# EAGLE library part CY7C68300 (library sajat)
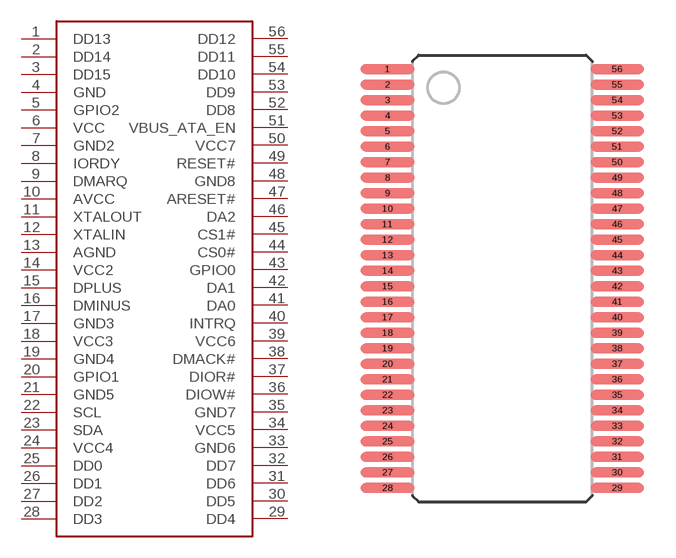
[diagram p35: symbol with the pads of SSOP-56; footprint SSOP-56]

Designator prefix -

## CY7C68300  [SSOP-56]
1  DD13
2  DD14
3  DD15
4  GND
5  GPIO2
6  VCC
7  GND2
8  IORDY
9  DMARQ
10  AVCC
11  XTALOUT
12  XTALIN
13  AGND
14  VCC2
15  DPLUS
16  DMINUS
17  GND3
18  VCC3
19  GND4
20  GPIO1
21  GND5
22  SCL
23  SDA
24  VCC4
25  DD0
26  DD1
27  DD2
28  DD3
29  DD4
30  DD5
31  DD6
32  DD7
33  GND6
34  VCC5
35  GND7
36  DIOW#
37  DIOR#
38  DMACK#
39  VCC6
40  INTRQ
41  DA0
42  DA1
43  GPIO0
44  CS0#
45  CS1#
46  DA2
47  ARESET#
48  GND8
49  RESET#
50  VCC7
51  VBUS_ATA_EN
52  DD8
53  DD9
54  DD10
55  DD11
56  DD12

## Footprint SSOP-56 (pad centres in mm)
56-lead Shrunk Small Outline Package SSOP56
smd 2.2 x 0.4: 1 -4.7,8.572; 2 -4.7,7.938; 3 -4.7,7.303; 4 -4.7,6.668; 5 -4.7,6.032; 6 -4.7,5.397; 7 -4.7,4.763; 8 -4.7,4.128; 9 -4.7,3.493; 10 -4.7,2.857; 11 -4.7,2.223; 12 -4.7,1.587; 13 -4.7,0.953; 14 -4.7,0.318; 15 -4.7,-0.318; 16 -4.7,-0.953; 17 -4.7,-1.587; 18 -4.7,-2.223; 19 -4.7,-2.857; 20 -4.7,-3.493; 21 -4.7,-4.128; 22 -4.7,-4.763; 23 -4.7,-5.397; 24 -4.7,-6.032; 25 -4.7,-6.668; 26 -4.7,-7.303; 27 -4.7,-7.938; 28 -4.7,-8.572; 29 4.7,-8.572; 30 4.7,-7.938; 31 4.7,-7.303; 32 4.7,-6.668; 33 4.7,-6.032; 34 4.7,-5.397; 35 4.7,-4.763; 36 4.7,-4.128; 37 4.7,-3.493; 38 4.7,-2.857; 39 4.7,-2.223; 40 4.7,-1.587; 41 4.7,-0.953; 42 4.7,-0.318; 43 4.7,0.318; 44 4.7,0.953; 45 4.7,1.587; 46 4.7,2.223; 47 4.7,2.857; 48 4.7,3.493; 49 4.7,4.128; 50 4.7,4.763; 51 4.7,5.397; 52 4.7,6.032; 53 4.7,6.668; 54 4.7,7.303; 55 4.7,7.938; 56 4.7,8.572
